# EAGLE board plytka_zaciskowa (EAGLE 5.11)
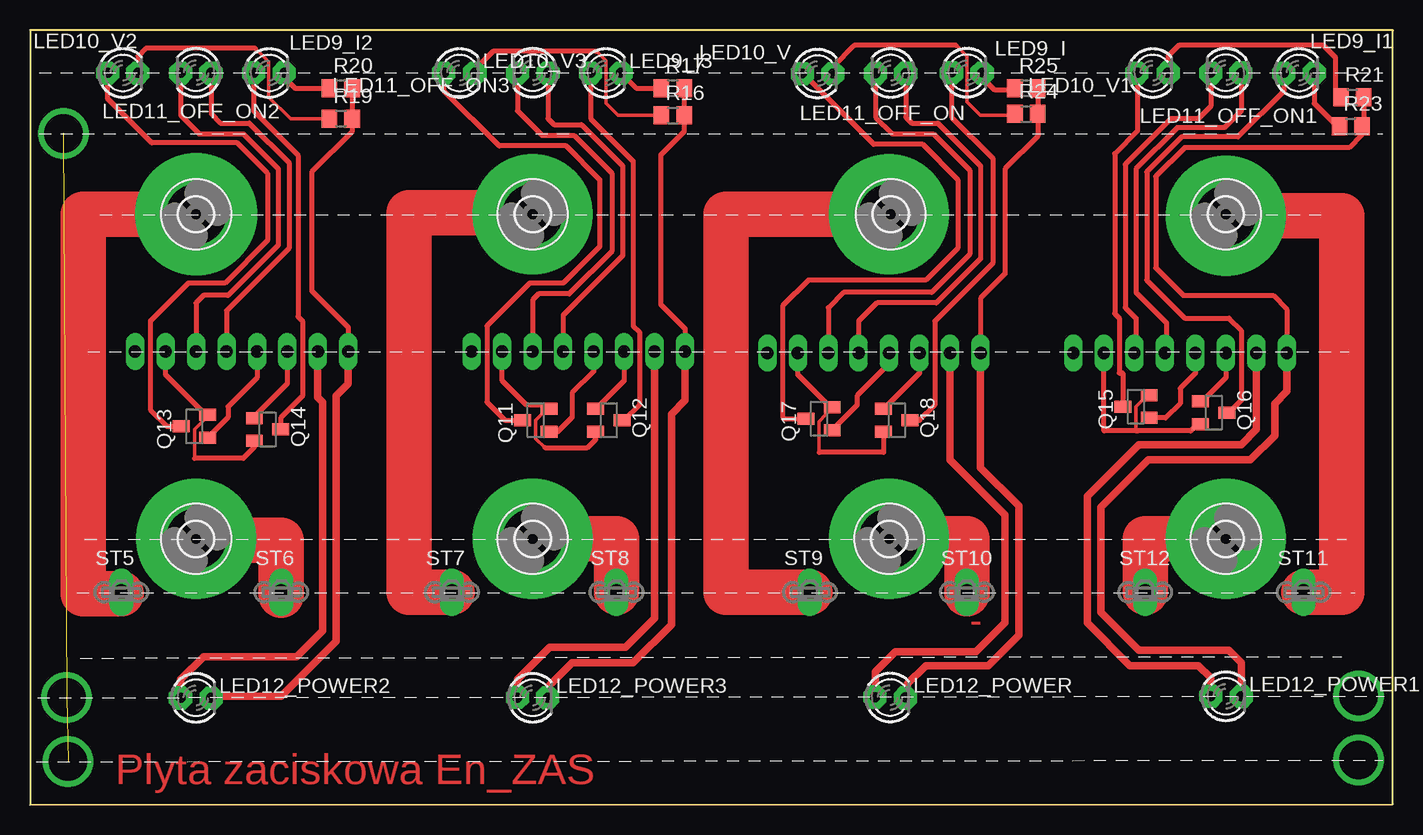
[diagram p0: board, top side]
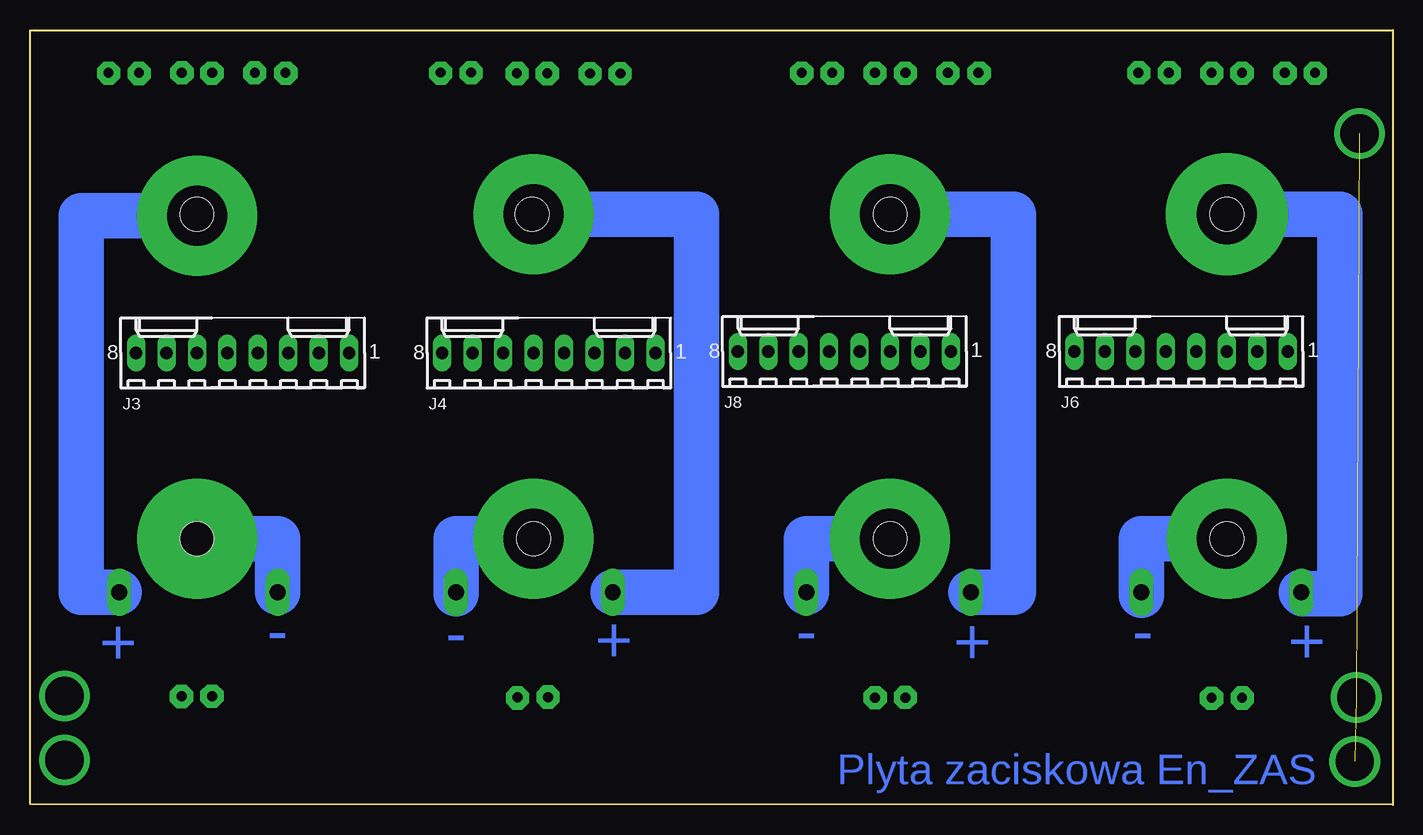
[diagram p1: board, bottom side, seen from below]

Size 113.61 x 64.57 mm. Coordinates in mm from the lower left corner, seen from the top.
Outline: 0,0 113.61,0.05 113.61,64.54 0,64.57 0,0
Copper layers (1*16): Top 0.035mm / dielectric 1.5mm / Bottom 0.035mm
Design rules "default": minimum track width 10mil, minimum drill 20mil, track to track 8mil, track to pad 8mil, pad to pad 8mil, via to via 8mil, smd to smd 8mil, copper to edge 1mil, drill to drill 8mil, minimum pad ring 10mil, minimum via ring 8mil, stop-mask expansion 4mil, vias tented up to drill 0mil, thermal gap 10mil

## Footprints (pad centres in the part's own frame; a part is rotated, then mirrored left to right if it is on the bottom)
2,8 = hole 2.8: 0,0
6410-08 = drill 1.016 long: 1 8.89,0; 2 6.35,0; 3 3.81,0; 4 1.27,0; 5 -1.27,0; 6 -3.81,0; 7 -6.35,0; 8 -8.89,0
LED3MM = drill 0.813 octagon: A -1.27,0; K 1.27,0
SOT23 = smd 1 x 1.4: 1 -0.95,-1.1; 2 0.95,-1.1; 3 0,1.1
R0805 = smd 1.3 x 1.5: 1 -0.95,0; 2 0.95,0
ST2,8 = drill 1.321 long: 1 0,0

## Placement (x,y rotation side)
H1  MOUNT-HOLE2.8  [2,8]  13.84,22.16 0 top
H2  MOUNT-HOLE2.8  [2,8]  13.84,49.21 0 top
H3  MOUNT-HOLE2.8  [2,8]  41.91,49.21 0 top
H4  MOUNT-HOLE2.8  [2,8]  41.91,22.16 0 top
H5  MOUNT-HOLE2.8  [2,8]  71.62,22.16 0 top
H6  MOUNT-HOLE2.8  [2,8]  71.75,49.21 0 top
H7  MOUNT-HOLE2.8  [2,8]  99.69,49.21 0 top
H8  MOUNT-HOLE2.8  [2,8]  99.69,22.16 0 top
J3  zlacze NS25-W8K  [6410-08]  95.88,37.65 0 bottom
J4  zlacze NS25-W8K  [6410-08]  70.35,37.65 0 bottom
J6  zlacze NS25-W8K  [6410-08]  17.65,37.78 0 bottom
J8  zlacze NS25-W8K  [6410-08]  45.72,37.78 0 bottom
LED9_I  [LED3MM]  78.1,61.02 0 top
LED9_I1  [LED3MM]  105.79,61 0 top
LED9_I2  [LED3MM]  19.93,61 0 top
LED9_I3  [LED3MM]  48,61 0 top
LED10_V  [LED3MM]  65.65,60.95 0 top
LED10_V1  [LED3MM]  93.59,61 0 top
LED10_V2  [LED3MM]  7.74,61 0 top
LED10_V3  [LED3MM]  35.81,61 0 top
LED11_OFF_ON  [LED3MM]  71.75,60.97 180 top
LED11_OFF_ON1  [LED3MM]  99.69,61 180 top
LED11_OFF_ON2  [LED3MM]  13.84,61 180 top
LED11_OFF_ON3  [LED3MM]  41.91,61 180 top
LED12_POWER  [LED3MM]  71.7,8.95 0 top
LED12_POWER1  [LED3MM]  99.69,9.05 0 top
LED12_POWER2  [LED3MM]  13.84,8.93 0 top
LED12_POWER3  [LED3MM]  41.91,8.93 0 top
Q11  BSS84  [SOT23]  42.16,32.04 90 top
Q12  BSS84  [SOT23]  48.25,32.04 270 top
Q13  BSS84  [SOT23]  13.71,31.53 90 top
Q14  BSS84  [SOT23]  19.81,31.28 270 top
Q15  BSS84  [SOT23]  92.2,33.18 90 top
Q16  BSS84  [SOT23]  98.67,32.68 270 top
Q17  BSS84  [SOT23]  65.78,32.17 90 top
Q18  BSS84  [SOT23]  72.26,32.04 270 top
R16  10k  [R0805]  53.59,57.44 0 top
R17  4k7  [R0805]  53.59,59.73 0 top
R19  4k7  [R0805]  25.9,57.19 0 top
R20  4k7  [R0805]  25.9,59.73 0 top
R21  4k7  [R0805]  110.23,58.96 0 top
R23  4k7  [R0805]  110.1,56.55 0 top
R24  4k7  [R0805]  83.05,57.57 0 top
R25  4k7  [R0805]  83.05,59.73 0 top
ST5  [ST2,8]  7.61,17.71 0 top
ST6  [ST2,8]  20.95,17.71 0 top
ST7  [ST2,8]  35.17,17.71 0 top
ST8  [ST2,8]  48.89,17.71 0 top
ST9  [ST2,8]  65.02,17.71 0 top
ST10  [ST2,8]  78.1,17.71 0 top
ST11  [ST2,8]  106.17,17.71 0 top
ST12  [ST2,8]  92.96,17.71 0 top

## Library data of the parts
H1-H8 = holes
J3 J4 J6 J8 = con-molex
LED9_I LED9_I1-LED9_I3 LED10_V LED10_V1-LED10_V3 LED11_OFF_ON LED11_OFF_ON1-LED11_OFF_ON3 LED12_POWER LED12_POWER1-LED12_POWER3 = led
Q11-Q18 = transistor-small-signal
R16 R17 R19-R21 R23-R25 = rcl
ST5-ST12 = con-rib

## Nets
+_1: ST5.1
+_2: ST7.1
+_3: ST9.1
+_4: ST11.1
-_1: ST6.1
-_2: ST8.1
-_3: ST10.1
-_4: ST12.1
GND_M: J8.8 LED12_POWER3.K R16.2 R17.2
GND_M1: J6.8 LED12_POWER2.K R19.2 R20.2
GND_M2: J3.8 LED12_POWER1.K R21.2 R23.2
GND_M3: J4.8 LED12_POWER.K R24.2 R25.2
N$9: LED10_V.K R24.1
N$20: LED9_I.K R25.1
N$24: LED9_I.A Q18.3
N$46: J4.7 LED12_POWER.A
N$53: J4.6 Q18.1
N$70: J4.3 LED11_OFF_ON.K
N$71: J4.4 LED11_OFF_ON.A
N$72: LED10_V1.A Q15.3
N$73: LED10_V1.K R21.1
N$74: LED9_I1.K R23.1
N$75: J3.7 LED12_POWER1.A
N$76: LED9_I1.A Q16.3
N$77: J3.3 LED11_OFF_ON1.K
N$78: J3.4 LED11_OFF_ON1.A
N$81: LED10_V2.A Q13.3
N$82: LED10_V2.K R19.1
N$83: LED9_I2.K R20.1
N$84: J6.7 LED12_POWER2.A
N$101: LED9_I2.A Q14.3
N$103: J6.3 LED11_OFF_ON2.K
N$114: J6.4 LED11_OFF_ON2.A
N$116: LED9_I3.K R17.1
N$117: LED9_I3.A Q12.3
N$118: J8.6 Q12.1
N$119: J8.7 LED12_POWER3.A
N$121: J8.5 Q11.1
N$122: J8.3 LED11_OFF_ON3.K
N$123: J8.4 LED11_OFF_ON3.A
N$129: J8.2 Q11.2 Q12.2
N$131: LED10_V3.A Q11.3
N$132: LED10_V3.K R16.1
N$133: J6.6 Q14.1
N$134: J6.5 Q13.1
N$135: J6.2 Q13.2 Q14.2
N$136: J3.6 Q16.1
N$137: J3.5 Q15.1
N$138: J3.2 Q15.2 Q16.2
N$139: J4.5 Q17.1
N$140: J4.2 Q17.2 Q18.2
N$141: LED10_V.A Q17.3

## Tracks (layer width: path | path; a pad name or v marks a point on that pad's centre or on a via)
+_1  (via drill 5 pad 10.16)
  Top 3.81: v13.84,49.21 4.44,49.21 4.44,17.59 7.61,17.59
  Bottom 3.81: v13.84,49.21 4.44,49.21 4.44,17.59 7.49,17.59 7.49,17.71 ST5.1
+_2  (via drill 5 pad 10)
  Top 3.81: 41.91,49.34 31.62,49.34 31.62,17.71 ST7.1
  Bottom 3.81: ST7.1 31.62,17.71 31.62,49.21 v41.91,49.21 41.91,49.08
+_3  (via drill 5 pad 10)
  Top 3.81: 71.75,49.21 58.03,49.21 58.03,17.71 ST9.1
  Bottom 3.81: ST9.1 58.03,17.71 58.03,49.21 v71.62,49.21
+_4  (via drill 5 pad 10)
  Top 3.81: v99.69,49.08 109.34,49.08 109.34,17.71 ST11.1
  Bottom 3.81: v99.69,49.08 109.34,49.08 109.34,17.71 ST11.1
-_1  (via drill 5 pad 10)
  Top 0.254: 20.95,18.98 21.58,18.98 ST6.1
  Top 3.81: 13.84,22.03 20.95,22.03 20.95,18.98 ST6.1 20.95,17.46
  Bottom 3.81: 13.46,22.16 v13.84,22.16 20.95,22.16 ST6.1 20.95,17.46
-_2  (via drill 5 pad 10)
  Top 3.81: v41.91,22.16 48.89,22.16 ST8.1
  Bottom 3.81: v41.91,22.16 48.89,22.16 ST8.1
-_3  (via drill 5 pad 10)
  Top 3.81: v71.62,22.16 78.1,22.16 78.1,17.59
  Bottom 3.81: 78.1,17.59 ST10.1 78.1,22.16 v71.62,22.16
-_4  (via drill 1 pad 10)
  Top 3.81: v99.69,22.16 92.96,22.16 ST12.1
  Bottom 3.81: v99.69,22.16 92.96,22.16 ST12.1
GND_M
  Top 0.406: R17.2 R16.2 | R16.2 54.54,57.25 54.6,57.19 | R16.2 54.54,56.1 52.57,54.14 52.57,41.69 54.6,39.66 J8.8
  Top 0.61: J8.8 54.6,33.69 53.46,32.55 53.46,15.02 50.29,11.85 45.21,11.85 43.17,9.82 LED12_POWER3.K
GND_M1
  Top 0.406: R20.2 R19.2 | R19.2 26.85,57.12 26.79,57.06 | R19.2 26.85,56.1 23.49,52.74 23.49,42.84 26.54,39.79 26.54,38.01 26.66,37.88 26.56,37.78 J6.8
  Top 0.61: J6.8 26.54,35.09 25.52,34.07 25.52,13.63 20.95,9.05 15.23,9.05 LED12_POWER2.K
GND_M2
  Top 0.406: 111.18,56.36 111.05,56.49 R23.2 | 111.18,56.36 R21.2 111.18,56.49 110.99,56.3 110.99,55.79 109.98,54.77 96.26,54.77 93.85,52.36 93.85,44.74 96.13,42.45 103.63,42.45 104.77,41.31 J3.8 | 111.18,56.36 111.37,56.17
  Top 0.61: J3.8 104.77,34.45 103.75,33.44 103.75,30.77 101.72,28.74 93.21,28.74 89.28,24.8 89.28,16.04 92.45,12.86 99.94,12.86 100.96,11.85 LED12_POWER1.K
GND_M3
  Top 0.406: R25.2 84,57.63 83.94,57.57 R24.2 84,55.72 81.28,53 81.28,44.23 79.24,42.2 J4.8 79.24,37.5
  Top 0.61: 79.24,37.5 79.24,28.1 82.42,24.93 82.42,14.13 79.88,11.59 74.67,11.59 73.15,10.07 73.15,9.18 73.27,9.05 73.17,8.95 LED12_POWER.K
N$9
  Top 0.305: 77.21,63.28 78.1,62.39 78.1,58.58 79.24,57.44 81.91,57.44
  Top 0.406: LED10_V.K 66.92,61.5 68.7,63.28 77.21,63.28 | 81.91,57.44 82.04,57.57 R24.1
N$20  (via drill 0.6 pad 1.93)
  Top 0.406: LED9_I.K v79.37,60.97 79.37,60.62 80.39,59.6 82.16,59.6 | 82.16,59.6 82.1,59.66 R25.1 | 82.16,59.6 82.29,59.47
N$24  (via drill 0.6 pad 1.93)
  Top 0.406: Q18.3 74.16,32.04 75.43,33.31 75.43,40.3 80.26,45.12 80.26,53.88 76.83,57.31 v76.83,61 LED9_I.A
N$46
  Top 0.61: J4.7 76.7,28.74 81.28,24.17 81.28,15.15 78.86,12.74 72.13,12.74 70.48,11.09 70.48,8.93 70.45,8.95 LED12_POWER.A
N$53
  Top 0.406: Q18.1 71.18,32.99 74.16,35.98 J4.6
N$70  (via drill 0.6 pad 1.93)
  Top 0.406: LED11_OFF_ON.K v70.48,60.95 70.48,57.31 71.88,55.92 75.31,55.92 78.35,52.87 78.35,45.88 75.18,42.71 67.81,42.71 66.54,41.44 J4.3
N$71
  Top 0.406: LED11_OFF_ON.A 73.02,57.31 73.53,56.81 75.69,56.81 79.24,53.25 79.24,45.5 75.56,41.82 70.61,41.82 69.08,40.3 J4.4 69.08,37.63
N$72
  Top 0.406: Q15.3 91.1,35.98 90.8,35.98 90.8,40.55 90.42,40.93 90.42,54.27 92.32,56.17 LED10_V1.A
N$73
  Top 0.406: LED10_V1.K 94.86,62.39 95.75,63.28 107.82,63.28 108.83,62.27 108.83,59.35 109.28,58.9 | 109.28,58.9 109.34,58.84 | R21.1 109.28,58.9
N$74  (via drill 0.6 pad 1.93)
  Top 0.406: R23.1 108.96,56.55 107.06,58.46 v107.06,60.97 LED9_I1.K
N$75
  Top 0.61: J3.7 102.23,31.28 100.96,30.01 92.45,30.01 88.13,25.69 88.13,15.15 91.69,11.59 97.4,11.59 98.42,10.58 LED12_POWER1.A
N$76  (via drill 0.6 pad 1.93)
  Top 0.406: LED9_I1.A v104.52,60.95 104.52,59.47 100.71,55.66 96.01,55.66 93.09,52.74 93.09,43.72 96.26,40.55 99.94,40.55 100.96,39.53 100.96,33.69 99.94,32.68 Q16.3
N$77
  Top 0.406: LED11_OFF_ON1.K 98.42,58.2 97.4,57.19 95.12,57.19 91.31,53.38 91.31,41.44 92.2,40.55 92.2,37.76 92.09,37.65 J3.3
N$78
  Top 0.406: LED11_OFF_ON1.A 100.96,57.82 99.56,56.42 95.63,56.42 92.2,53 92.2,42.71 94.74,40.17 94.74,37.76 94.63,37.65 J3.4
N$81  (via drill 0.6 pad 1.93)
  Top 0.406: LED10_V2.A v6.47,60.97 6.47,58.84 10.15,55.15 17.27,55.15 19.81,52.61 19.81,47.03 16.25,43.47 13.2,43.47 10.03,40.3 10.03,32.93 11.42,31.53 12.57,31.53 12.61,31.49 | 12.61,31.49 12.69,31.41 | 12.61,31.49 Q13.3
N$82
  Top 0.305: 18.79,63.03 19.91,61.91 19.91,58.96 21.71,57.19 R19.1
  Top 0.406: LED10_V2.K 9.01,62.39 9.65,63.03 18.79,63.03
N$83
  Top 0.406: LED9_I2.K 21.2,60.62 22.09,59.73 R20.1 25.01,59.73
N$84
  Top 0.61: J6.7 24,33.95 24.38,33.56 24.38,14.51 22.22,12.36 14.47,12.36 12.57,10.45 LED12_POWER2.A
N$101
  Top 0.406: Q14.3 20.91,32.25 22.73,34.07 22.73,40.3 22.35,40.68 22.35,54.14 18.66,57.82 18.66,60.74 18.79,60.87 LED9_I2.A
N$103  (via drill 0.6 pad 1.93)
  Top 0.406: J6.3 13.84,41.82 14.47,42.45 16.5,42.45 20.7,46.65 20.7,53 17.77,55.92 14.09,55.92 12.57,57.44 v12.57,60.97 LED11_OFF_ON2.K
N$114
  Top 0.406: LED11_OFF_ON2.A 15.11,57.57 15.87,56.81 18.28,56.81 21.58,53.5 21.58,46.39 16.38,41.18 J6.4
N$116
  Top 0.406: LED9_I3.K 50.54,59.73 R17.1
N$117  (via drill 0.6 pad 1.93)
  Top 0.406: LED9_I3.A v46.73,60.97 46.73,57.19 50.29,53.63 50.29,39.91 50.8,39.41 50.8,33.31 49.52,32.04 Q12.3
N$118
  Top 0.406: Q12.1 47.17,32.99 49.52,35.34 J8.6
N$119  (via drill 0.6 pad 1.93)
  Top 0.61: J8.7 52.06,15.53 49.65,13.12 43.3,13.12 40.63,10.45 v40.63,8.95 LED12_POWER3.A
N$121
  Top 0.406: J8.5 46.98,36.1 45.21,34.33 45.21,32.29 43.94,31.02 43.43,31.02 43.36,31.09 Q11.1
N$122  (via drill 0.6 pad 1.93)
  Top 0.406: J8.3 41.91,42.07 42.41,42.58 44.95,42.58 48.51,46.14 48.51,52.61 45.33,55.79 42.67,55.79 40.63,57.82 v40.63,60.97 LED11_OFF_ON3.K
N$123  (via drill 0.6 pad 1.93)
  Top 0.406: LED11_OFF_ON3.A v43.17,60.97 43.17,57.19 43.68,56.68 45.97,56.68 49.4,53.25 49.4,45.76 44.44,40.8 J8.4
N$127  (via drill 3.2 pad 4)
  other vias: 110.74,3.74
N$129
  Top 0.305: 42.92,29.75 42.16,30.52 42.16,32.04 43.17,33.06
  Top 0.406: J8.2 39.36,35.34 41.4,33.31 42.92,33.31 43.17,33.06 | 43.26,32.97 43.43,32.8 | 43.26,32.97 Q11.2 43.24,32.99 43.17,33.06 | 43.26,32.97 43.17,33.06 | Q12.2 47.16,30.43 46.48,29.75 42.92,29.75
N$131
  Top 0.406: LED10_V3.A 34.54,59.47 39.11,54.9 44.7,54.9 47.49,52.11 47.49,46.52 44.44,43.47 41.65,43.47 38.09,39.91 38.09,33.56 39.62,32.04 Q11.3 | Q11.3 41.14,32.04 | Q11.3 41.4,32.04
N$132
  Top 0.305: 47.24,62.77 48,62.01 48,58.46 49.02,57.44 R16.1
  Top 0.406: LED10_V3.K 37.08,61.25 38.6,62.77 47.24,62.77
N$133
  Top 0.406: Q14.1 18.71,32.25 18.66,32.29 21.46,35.09 J6.6
N$134
  Top 0.406: J6.5 18.92,35.6 16.5,33.18 16.5,32.29 14.81,30.6 Q13.1
N$135
  Top 0.305: 13.71,28.87 13.71,31.28 14.85,32.42
  Top 0.406: J6.2 11.3,35.85 14.73,32.42 14.79,32.48 Q13.2 14.81,32.46 14.85,32.42 | Q14.2 18.71,29.8 17.77,28.87 13.71,28.87
N$136
  Top 0.406: Q16.1 97.6,33.63 97.66,33.56 99.69,35.6 J3.6
N$137
  Top 0.406: Q15.1 94.68,32.23 95.88,33.44 95.88,34.71 97.15,35.98 J3.5
N$138
  Top 0.305: 93.15,34.13 92.2,33.18 92.2,31.15
  Top 0.406: Q16.2 97.47,31.73 97.4,31.79 96.77,31.15 92.32,31.15 | 92.32,31.15 92.2,31.15 | 93.15,34.13 Q15.2 | J3.2 89.53,31.15 92.32,31.15
N$139
  Top 0.406: J4.5 71.62,36.74 68.96,34.07 68.96,33.31 66.88,31.24 Q17.1
N$140
  Top 0.305: 65.78,29.37 65.78,31.91 66.88,33.14
  Top 0.406: J4.2 64,35.85 66.8,33.06 66.86,33.12 Q17.2 66.88,33.14 66.92,33.18 | Q18.2 71.16,29.37 65.78,29.37
N$141
  Top 0.406: LED10_V.A 64.44,60.95 70.35,55.03 74.42,55.03 77.34,52.11 77.34,46.39 74.67,43.72 64.89,43.72 62.73,41.57 62.73,32.29 62.86,32.17 Q17.3 64.89,32.17
S$1  (via drill 0.6 pad 1.93)
  other vias: 8.99,60.97
S$2  (via drill 3.2 pad 4)
  other vias: 110.74,9.08
S$3  (via drill 0.6 pad 1.93)
  other vias: 15.08,60.97
S$4  (via drill 0.6 pad 1.93)
  other vias: 18.64,61
S$5  (via drill 0.6 pad 1.93)
  other vias: 21.18,61
S$6  (via drill 0.6 pad 1.93)
  other vias: 34.49,60.97
S$7  (via drill 0.6 pad 1.93)
  other vias: 37.08,60.97
S$8  (via drill 0.6 pad 1.93)
  other vias: 49.27,60.97
S$9  (via drill 0.6 pad 1.93)
  other vias: 64.41,60.92
S$10  (via drill 0.6 pad 1.93)
  other vias: 66.92,60.92
S$11  (via drill 0.6 pad 1.93)
  other vias: 72.99,60.95
S$12  (via drill 0.6 pad 1.93)
  other vias: 92.27,60.97
S$13  (via drill 0.6 pad 1.93)
  other vias: 94.89,61
S$14  (via drill 0.6 pad 1.93)
  other vias: 98.45,60.97
S$15  (via drill 0.6 pad 1.93)
  other vias: 100.93,61
S$16  (via drill 0.6 pad 1.93)
  other vias: 100.99,9.03
S$17  (via drill 0.6 pad 1.93)
  other vias: 98.45,9.05
S$18  (via drill 0.6 pad 1.93)
  other vias: 72.97,8.9
S$19  (via drill 0.6 pad 1.93)
  other vias: 70.43,8.98
S$20  (via drill 0.6 pad 1.93)
  other vias: 43.15,8.93
S$21  (via drill 0.6 pad 1.93)
  other vias: 12.54,8.9
S$22  (via drill 0.6 pad 1.93)
  other vias: 15.11,8.88
S$51  (via drill 3.2 pad 4)  (2 unrouted)
  Top 0.254: v2.79,55.94 2.53,57.08
  other vias: 3.17,3.62 3.04,8.95

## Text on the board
Top: - | Plyta zaciskowa En_ZAS
Bottom: - | - | - | + | + | + | - | + | Plyta zaciskowa En_ZAS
